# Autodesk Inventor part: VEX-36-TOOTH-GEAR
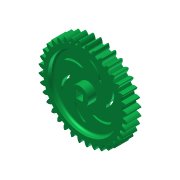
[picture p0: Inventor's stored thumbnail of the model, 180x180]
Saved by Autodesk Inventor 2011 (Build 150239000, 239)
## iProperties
Created: 2007-08
Part Number: VEX-36-TOOTH-GEAR
Material: ABS Plastic
Document SubType Name: Modeling
Density: 1.06 g/cm^3
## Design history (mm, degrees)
feature "Base1"
workaxis "Work Axis1"
sketch "Sketch1"
  geometry: L1 (1.612, 1.362)-(1.612, 1.231) reference; L2 (1.558, 1.177)-(1.612, 1.231) reference; L3 (1.613, 1.104)-(1.558, 1.159) reference; L4 (1.613, 1.104)-(1.612, 1.079) reference; L5 (1.558, 1.024)-(1.612, 1.079) reference; L6 (1.558, 1.007)-(1.612, 0.952) reference; L7 (1.612, 0.952)-(1.612, -0.952) reference; L8 (1.612, -0.952)-(1.558, -1.007) reference; L9 (1.613, -1.079)-(1.558, -1.024) reference; L10 (1.613, -1.079)-(1.612, -1.105) reference; L11 (1.558, -1.159)-(1.612, -1.105) reference; L12 (1.613, -1.231)-(1.558, -1.177) reference; L13 (1.613, -1.231)-(1.612, -1.362) reference; L14 (1.362, -1.612)-(1.231, -1.612) reference; L15 (1.177, -1.558)-(1.231, -1.612) reference; L16 (1.104, -1.613)-(1.159, -1.558) reference; L17 (1.104, -1.613)-(1.079, -1.612) reference; L18 (1.024, -1.558)-(1.079, -1.612) reference; L19 (1.007, -1.558)-(0.952, -1.612) reference; L20 (0.952, -1.612)-(-0.952, -1.612) reference; L21 (-0.952, -1.612)-(-1.007, -1.558) reference; L22 (-1.079, -1.613)-(-1.024, -1.558) reference; L23 (-1.079, -1.613)-(-1.105, -1.612) reference; L24 (-1.159, -1.558)-(-1.105, -1.612) reference; L25 (-1.231, -1.613)-(-1.177, -1.558) reference; L26 (-1.231, -1.613)-(-1.362, -1.612) reference; L27 (-1.612, -1.362)-(-1.612, -1.231) reference; L28 (-1.558, -1.177)-(-1.612, -1.231) reference; L29 (-1.613, -1.104)-(-1.558, -1.159) reference; L30 (-1.613, -1.104)-(-1.612, -1.079) reference; L31 (-1.558, -1.024)-(-1.612, -1.079) reference; L32 (-1.558, -1.007)-(-1.612, -0.952) reference; L33 (-1.612, -0.952)-(-1.612, 0.952) reference; L34 (-1.612, 0.952)-(-1.558, 1.007) reference; L35 (-1.613, 1.079)-(-1.558, 1.024) reference; L36 (-1.613, 1.079)-(-1.612, 1.105) reference; L37 (-1.558, 1.159)-(-1.612, 1.105) reference; L38 (-1.613, 1.231)-(-1.558, 1.177) reference; L39 (-1.613, 1.231)-(-1.612, 1.362) reference; L40 (-1.362, 1.612)-(-1.231, 1.612) reference; L41 (-1.177, 1.558)-(-1.231, 1.612) reference; L42 (-1.104, 1.613)-(-1.159, 1.558) reference; L43 (-1.104, 1.613)-(-1.079, 1.612) reference; L44 (-1.024, 1.558)-(-1.079, 1.612) reference; L45 (-1.007, 1.558)-(-0.952, 1.612) reference; L46 (-0.952, 1.612)-(0.952, 1.612) reference; L47 (0.952, 1.612)-(1.007, 1.558) reference; L48 (1.079, 1.613)-(1.024, 1.558) reference; L49 (1.079, 1.613)-(1.105, 1.612) reference; L50 (1.159, 1.558)-(1.105, 1.612) reference; L51 (1.231, 1.613)-(1.177, 1.558) reference; L52 (1.231, 1.613)-(1.362, 1.612) reference; L53 (0, 0)-(19.421, -5.197); C1 r 4 at (0, 0) reference; A1 r 0.25 centre (1.362, 1.362) between (1.612, 1.362) and (1.362, 1.612) reference; A2 r 0.012 centre (1.566, 1.168) between (1.558, 1.177) and (1.558, 1.159) reference; A3 r 0.012 centre (1.566, 1.016) between (1.558, 1.024) and (1.558, 1.007) reference; A4 r 0.012 centre (1.566, -1.016) between (1.558, -1.007) and (1.558, -1.024) reference; A5 r 0.013 centre (1.567, -1.168) between (1.558, -1.159) and (1.558, -1.177) reference; A6 r 0.25 centre (1.362, -1.362) between (1.362, -1.612) and (1.612, -1.362) reference; A7 r 0.012 centre (1.168, -1.566) between (1.177, -1.558) and (1.159, -1.558) reference; A8 r 0.012 centre (1.016, -1.566) between (1.024, -1.558) and (1.007, -1.558) reference; A9 r 0.012 centre (-1.016, -1.566) between (-1.007, -1.558) and (-1.024, -1.558) reference; A10 r 0.013 centre (-1.168, -1.567) between (-1.159, -1.558) and (-1.177, -1.558) reference; A11 r 0.25 centre (-1.362, -1.362) between (-1.612, -1.362) and (-1.362, -1.612) reference; A12 r 0.012 centre (-1.566, -1.168) between (-1.558, -1.177) and (-1.558, -1.159) reference; A13 r 0.012 centre (-1.566, -1.016) between (-1.558, -1.024) and (-1.558, -1.007) reference; A14 r 0.012 centre (-1.566, 1.016) between (-1.558, 1.007) and (-1.558, 1.024) reference; A15 r 0.013 centre (-1.567, 1.168) between (-1.558, 1.159) and (-1.558, 1.177) reference; A16 r 0.25 centre (-1.362, 1.362) between (-1.362, 1.612) and (-1.612, 1.362) reference; A17 r 0.012 centre (-1.168, 1.566) between (-1.177, 1.558) and (-1.159, 1.558) reference; A18 r 0.012 centre (-1.016, 1.566) between (-1.024, 1.558) and (-1.007, 1.558) reference; A19 r 0.012 centre (1.016, 1.566) between (1.007, 1.558) and (1.024, 1.558) reference; A20 r 0.013 centre (1.168, 1.567) between (1.159, 1.558) and (1.177, 1.558) reference; A21 r 20.104 centre (0, 0) between (19.373, -5.373) and (19.464, -5.034) reference; 1 further point
  constraints: 2 end point, 1 point on circle, 1 point on line
workplane "Work Plane1"
sketch "Sketch2"
  geometry: L1 (1.612, 1.362)-(1.612, 1.231) reference; L2 (1.558, 1.177)-(1.612, 1.231) reference; L3 (1.613, 1.104)-(1.558, 1.159) reference; L4 (1.613, 1.104)-(1.612, 1.079) reference; L5 (1.558, 1.024)-(1.612, 1.079) reference; L6 (1.558, 1.007)-(1.612, 0.952) reference; L7 (1.612, 0.952)-(1.612, -0.952) reference; L8 (1.612, -0.952)-(1.558, -1.007) reference; L9 (1.613, -1.079)-(1.558, -1.024) reference; L10 (1.613, -1.079)-(1.612, -1.105) reference; L11 (1.558, -1.159)-(1.612, -1.105) reference; L12 (1.613, -1.231)-(1.558, -1.177) reference; L13 (1.613, -1.231)-(1.612, -1.362) reference; L14 (1.362, -1.612)-(1.231, -1.612) reference; L15 (1.177, -1.558)-(1.231, -1.612) reference; L16 (1.104, -1.613)-(1.159, -1.558) reference; L17 (1.104, -1.613)-(1.079, -1.612) reference; L18 (1.024, -1.558)-(1.079, -1.612) reference; L19 (1.007, -1.558)-(0.952, -1.612) reference; L20 (0.952, -1.612)-(-0.952, -1.612) reference; L21 (-0.952, -1.612)-(-1.007, -1.558) reference; L22 (-1.079, -1.613)-(-1.024, -1.558) reference; L23 (-1.079, -1.613)-(-1.105, -1.612) reference; L24 (-1.159, -1.558)-(-1.105, -1.612) reference; L25 (-1.231, -1.613)-(-1.177, -1.558) reference; L26 (-1.231, -1.613)-(-1.362, -1.612) reference; L27 (-1.612, -1.362)-(-1.612, -1.231) reference; L28 (-1.558, -1.177)-(-1.612, -1.231) reference; L29 (-1.613, -1.104)-(-1.558, -1.159) reference; L30 (-1.613, -1.104)-(-1.612, -1.079) reference; L31 (-1.558, -1.024)-(-1.612, -1.079) reference; L32 (-1.558, -1.007)-(-1.612, -0.952) reference; L33 (-1.612, -0.952)-(-1.612, 0.952) reference; L34 (-1.612, 0.952)-(-1.558, 1.007) reference; L35 (-1.613, 1.079)-(-1.558, 1.024) reference; L36 (-1.613, 1.079)-(-1.612, 1.105) reference; L37 (-1.558, 1.159)-(-1.612, 1.105) reference; L38 (-1.613, 1.231)-(-1.558, 1.177) reference; L39 (-1.613, 1.231)-(-1.612, 1.362) reference; L40 (-1.362, 1.612)-(-1.231, 1.612) reference; L41 (-1.177, 1.558)-(-1.231, 1.612) reference; L42 (-1.104, 1.613)-(-1.159, 1.558) reference; L43 (-1.104, 1.613)-(-1.079, 1.612) reference; L44 (-1.024, 1.558)-(-1.079, 1.612) reference; L45 (-1.007, 1.558)-(-0.952, 1.612) reference; L46 (-0.952, 1.612)-(0.952, 1.612) reference; L47 (0.952, 1.612)-(1.007, 1.558) reference; L48 (1.079, 1.613)-(1.024, 1.558) reference; L49 (1.079, 1.613)-(1.105, 1.612) reference; L50 (1.159, 1.558)-(1.105, 1.612) reference; L51 (1.231, 1.613)-(1.177, 1.558) reference; L52 (1.231, 1.613)-(1.362, 1.612) reference; L53 (0, 0)-(16.91, -6.128); C1 r 4 at (0, 0) reference; A1 r 0.25 centre (1.362, 1.362) between (1.612, 1.362) and (1.362, 1.612) reference; A2 r 0.012 centre (1.566, 1.168) between (1.558, 1.177) and (1.558, 1.159) reference; A3 r 0.012 centre (1.566, 1.016) between (1.558, 1.024) and (1.558, 1.007) reference; A4 r 0.012 centre (1.566, -1.016) between (1.558, -1.007) and (1.558, -1.024) reference; A5 r 0.013 centre (1.567, -1.168) between (1.558, -1.159) and (1.558, -1.177) reference; A6 r 0.25 centre (1.362, -1.362) between (1.362, -1.612) and (1.612, -1.362) reference; A7 r 0.012 centre (1.168, -1.566) between (1.177, -1.558) and (1.159, -1.558) reference; A8 r 0.012 centre (1.016, -1.566) between (1.024, -1.558) and (1.007, -1.558) reference; A9 r 0.012 centre (-1.016, -1.566) between (-1.007, -1.558) and (-1.024, -1.558) reference; A10 r 0.013 centre (-1.168, -1.567) between (-1.159, -1.558) and (-1.177, -1.558) reference; A11 r 0.25 centre (-1.362, -1.362) between (-1.612, -1.362) and (-1.362, -1.612) reference; A12 r 0.012 centre (-1.566, -1.168) between (-1.558, -1.177) and (-1.558, -1.159) reference; A13 r 0.012 centre (-1.566, -1.016) between (-1.558, -1.024) and (-1.558, -1.007) reference; A14 r 0.012 centre (-1.566, 1.016) between (-1.558, 1.007) and (-1.558, 1.024) reference; A15 r 0.013 centre (-1.567, 1.168) between (-1.558, 1.159) and (-1.558, 1.177) reference; A16 r 0.25 centre (-1.362, 1.362) between (-1.362, 1.612) and (-1.612, 1.362) reference; A17 r 0.012 centre (-1.168, 1.566) between (-1.177, 1.558) and (-1.159, 1.558) reference; A18 r 0.012 centre (-1.016, 1.566) between (-1.024, 1.558) and (-1.007, 1.558) reference; A19 r 0.012 centre (1.016, 1.566) between (1.007, 1.558) and (1.024, 1.558) reference; A20 r 0.013 centre (1.168, 1.567) between (1.159, 1.558) and (1.177, 1.558) reference; A21 r 17.986 centre (0, 0) between (16.676, -6.738) and (17.106, -5.558) reference; 1 further point
  constraints: 2 end point, 1 point on circle, 1 point on line
workplane "Work Plane2"
body "Solid1"
